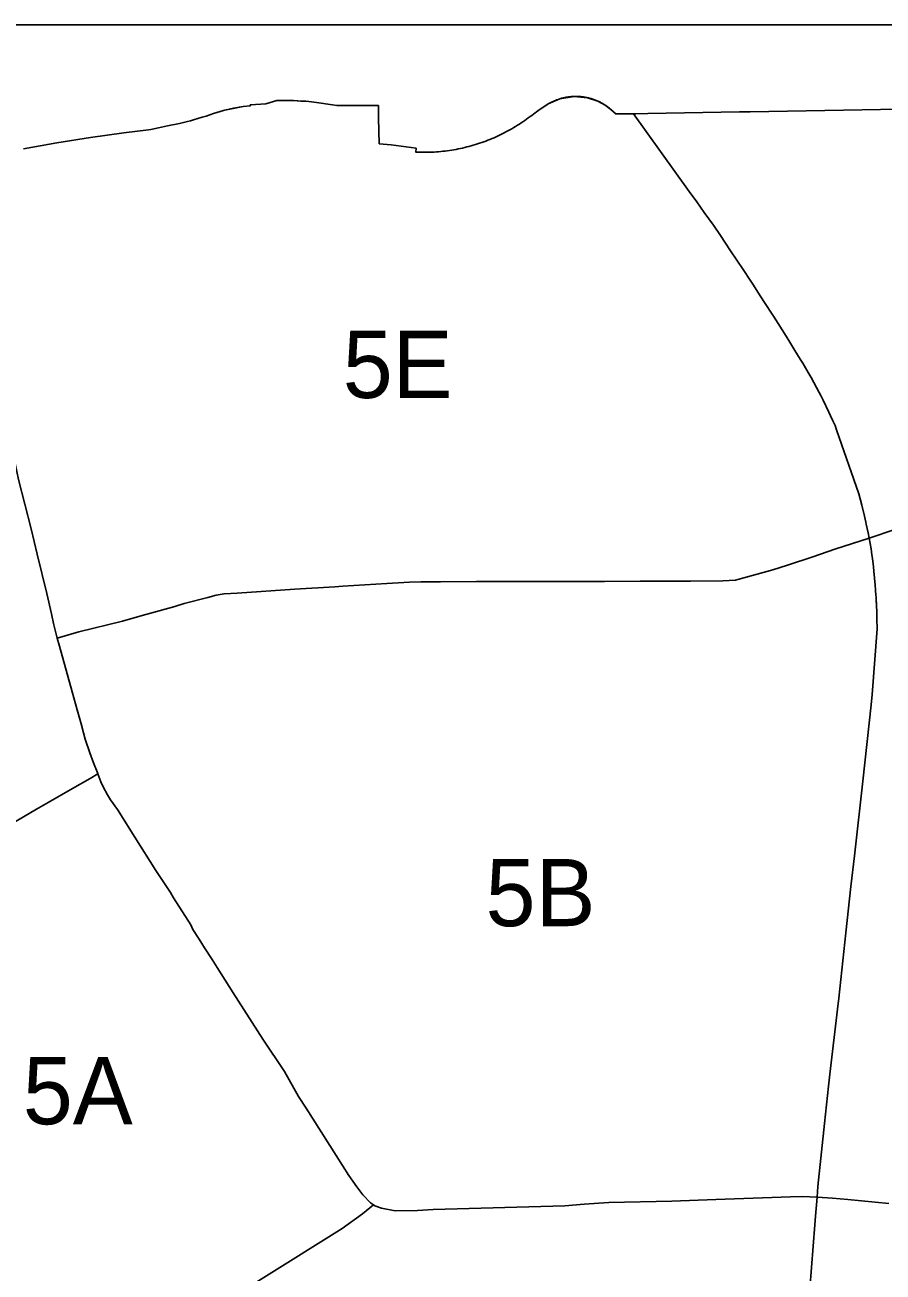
# Model space of a CAD drawing. Extents: x 152750 to 166250, y 378996 to 390000.
# Drawn here: x 159576 to 162130, y 386288 to 390000 of the extents above; entities that cross this region are included whole.
import ezdxf

# ---------------------------------------------------------------- set-up
doc = ezdxf.new("R2010")
doc.units = 0
doc.layers.add('BLT_Nummers', color=7, linetype='Continuous')
doc.layers.add('BLT_Shapes', color=7, linetype='Continuous')

msp = doc.modelspace()

# ---------------------------------------------------------------- linework, layer by layer
at = {"layer": 'BLT_Shapes'}
for p, q in [((163502.8, 390000), (157101, 390000)), ((160247.2, 389762.7), (160246.8, 389759.5)), ((160325.7, 389775.2), (160375.6, 389775.4)), ((160375.6, 389775.4), (160397.3, 389773.2)), ((160397.3, 389773.2), (160401, 389772.7)), ((160504.2, 389760.5), (160611.4, 389760.6)), ((160611.4, 389760.6), (160628.2, 389760.6)), ((161126.8, 389760.5), (161129.2, 389761.9)), ((161146, 389771.2), (161148.4, 389772.4)), ((161148.4, 389772.4), (161150.9, 389773.5)), ((161150.9, 389773.5), (161153.3, 389774.5)), ((161153.3, 389774.5), (161155.8, 389775.6)), ((161160.8, 389777.5), (161163.3, 389778.4)), ((161168.5, 389780.1), (161171, 389780.9)), ((161178.8, 389782.9), (161181.4, 389783.5)), ((161181.4, 389783.5), (161184.1, 389784.1)), ((161184.1, 389784.1), (161186.7, 389784.6)), ((161186.7, 389784.6), (161189.4, 389785.1)), ((161189.4, 389785.1), (161192, 389785.5)), ((161208.1, 389787.1), (161210.8, 389787.2)), ((161210.8, 389787.2), (161213.5, 389787.3)), ((161218.8, 389787.3), (161221.5, 389787.2)), ((161250.9, 389783.5), (161253.5, 389782.8)), ((161258.8, 389781.5), (161261.3, 389780.8)), ((161266.5, 389779.1), (161269, 389778.3)), ((161276.6, 389775.4), (161279.1, 389774.3)), ((161279.1, 389774.3), (161281.6, 389773.2)), ((161300.6, 389763), (161303.4, 389761.2)), ((161303.4, 389761.2), (161305.1, 389760.1)), ((160225.6, 389757.5), (160171.1, 389746.7)), ((160196.7, 389752.4), (160225.6, 389757.5)), ((160246.8, 389759.5), (160225.6, 389757.5)), ((161097.9, 389740.4), (161099.2, 389741.4)), ((161099.2, 389741.4), (161097.9, 389740.4)), ((161099.2, 389741.4), (161103.3, 389744.4)), ((161103.3, 389744.4), (161099.2, 389741.4)), ((161103.3, 389744.4), (161104.7, 389745.4)), ((161121.2, 389756.8), (161124.4, 389758.9)), ((161124.4, 389758.9), (161126.8, 389760.5)), ((161305.1, 389760.1), (161307.4, 389758.6)), ((161307.4, 389758.6), (161309.6, 389757)), ((161309.6, 389757), (161311.7, 389755.4)), ((161321.8, 389747.1), (161324.1, 389745.1)), ((161334.5, 389735), (161358.3, 389735.2)), ((161358.3, 389735.2), (161394, 389735.8)), ((161388, 389735.7), (161358.3, 389735.2)), ((161394, 389735.8), (161388, 389735.7)), ((161734.5, 389741.6), (161703, 389741.1)), ((159870.9, 389678.6), (159943.4, 389687.3)), ((159943.4, 389687.3), (159870.9, 389678.6)), ((159943.4, 389687.3), (159950.8, 389688.6)), ((159950.8, 389688.6), (159943.4, 389687.3)), ((159950.8, 389688.6), (159973.2, 389693.5)), ((159973.2, 389693.5), (159950.8, 389688.6)), ((159973.2, 389693.5), (160000, 389699.3)), ((160000, 389699.3), (159973.2, 389693.5)), ((160000, 389699.3), (160036.1, 389707.1)), ((160036.1, 389707.1), (160000, 389699.3)), ((160036.1, 389707.1), (160059.8, 389712.5)), ((160059.8, 389712.5), (160036.1, 389707.1)), ((161013.8, 389684.6), (161019.6, 389687.8)), ((161019.6, 389687.8), (161013.8, 389684.6)), ((160929.5, 389647.8), (160935.7, 389649.9)), ((160935.7, 389649.9), (160929.5, 389647.8)), ((160954.2, 389656.8), (160960.3, 389659.2)), ((160960.3, 389659.2), (160954.2, 389656.8)), ((160972.5, 389664.3), (160978.5, 389667)), ((160978.5, 389667), (160972.5, 389664.3)), ((160978.5, 389667), (160984.5, 389669.8)), ((160984.5, 389669.8), (160978.5, 389667)), ((159571.7, 389630.9), (159670.9, 389648.8)), ((159670.9, 389648.8), (159571.7, 389630.9)), ((160630.1, 389646.2), (160665.8, 389643.2)), ((160665.8, 389643.2), (160630.1, 389646.2)), ((160665.8, 389643.2), (160740.4, 389633.4)), ((160740.4, 389633.4), (160665.8, 389643.2)), ((160739.6, 389621.5), (160740.4, 389633.4)), ((160743.8, 389621.3), (160739.6, 389621.5)), ((160743.8, 389621.3), (160749.3, 389621.1)), ((160749.3, 389621.1), (160743.8, 389621.3)), ((160749.3, 389621.1), (160754.6, 389621)), ((160754.6, 389621), (160749.3, 389621.1)), ((160754.6, 389621), (160761.2, 389620.9)), ((160761.2, 389620.9), (160754.6, 389621)), ((160780.9, 389621.2), (160787.5, 389621.4)), ((160787.5, 389621.4), (160780.9, 389621.2)), ((160846.4, 389627.4), (160852.9, 389628.5)), ((160852.9, 389628.5), (160846.4, 389627.4)), ((161734.4, 389240.7), (161713.9, 389272.1)), ((161841.6, 389073.8), (161817.8, 389111.4)), ((161883.8, 389005.6), (161868.1, 389031)), ((161969.4, 388847.1), (161952.1, 388883)), ((161987.4, 388808.1), (161981, 388821.9)), ((161992.1, 388795.3), (161987.4, 388808.1)), ((162058.3, 388604.2), (161992.1, 388795.3)), ((162062.5, 388589.2), (162058.3, 388604.2)), ((162067.5, 388570.9), (162062.5, 388589.2)), ((162075.6, 388537.8), (162067.5, 388570.9)), ((162079.5, 388519.6), (162075.6, 388537.8)), ((162088.6, 388472.8), (162086, 388487.8)), ((162088.6, 388472.8), (162091.6, 388456.1)), ((161802.6, 388377.8), (161845.7, 388391.9)), ((161845.7, 388391.9), (161921.4, 388416.6)), ((162101.9, 388387.2), (162103.2, 388374.1)), ((160379.8, 388320.8), (160498.3, 388327.6)), ((160498.3, 388327.6), (160522.5, 388329.3)), ((161301.7, 388343.8), (161407.8, 388344.5)), ((161407.8, 388344.5), (161556.9, 388344.5)), ((161556.9, 388344.5), (161653.1, 388345.8)), ((161653.1, 388345.8), (161690.8, 388347.7)), ((162108.2, 388318), (162108.4, 388315.4)), ((162108.4, 388315.4), (162109.2, 388305.2)), ((159672.4, 388174.9), (159736.1, 388194.1)), ((159678.6, 388150.5), (159672.4, 388174.9)), ((159769.3, 387833.5), (159755.7, 387874.5)), ((159792.8, 387771.2), (159792.7, 387771.5)), ((159532.8, 387620.6), (159610.8, 387665.5)), ((160008.9, 387417.8), (160018.3, 387401.9)), ((160018.3, 387401.9), (160069.7, 387321.9)), ((160563.9, 386541.9), (160581.5, 386517.5)), ((161933.9, 386510.6), (161890.7, 386512.8)), ((161890.7, 386512.8), (161933.9, 386510.6)), ((162025.7, 386503.7), (162147.9, 386491.8))]:
    msp.add_line(p, q, dxfattribs=at)
for points in [[(160225.6, 389757.5), (160246.8, 389759.5), (160247.2, 389762.7), (160293.4, 389765.6), (160325.7, 389775.2)], [(160325.7, 389775.2), (160293.4, 389765.6), (160247.2, 389762.7)], [(160401, 389772.7), (160375.6, 389775.4), (160325.7, 389775.2)], [(160401, 389772.7), (160411.9, 389773.4), (160420.8, 389772.2)], [(160420.8, 389772.2), (160411.9, 389773.4), (160401, 389772.7)], [(160420.8, 389772.2), (160444.1, 389769.3), (160491.5, 389762.4), (160504.2, 389760.5)], [(160504.2, 389760.5), (160491.5, 389762.4), (160444.1, 389769.3), (160420.8, 389772.2)], [(160628.2, 389760.6), (160611.4, 389760.6), (160504.2, 389760.5)], [(160628.2, 389760.6), (160628.8, 389723.1), (160630.1, 389646.2)], [(160630.1, 389646.2), (160628.8, 389723.1), (160628.2, 389760.6)], [(161328.3, 389741.1), (161319.9, 389748.8), (161303.4, 389761.2), (161281.6, 389773.2), (161250.9, 389783.5), (161210.8, 389787.2), (161168.5, 389780.1), (161133.9, 389764.8), (161103.3, 389744.4)], [(161129.2, 389761.9), (161131.6, 389763.4), (161133.9, 389764.8), (161135.6, 389765.7), (161137.4, 389766.7), (161139.5, 389767.9), (161141.5, 389768.9), (161143.6, 389770), (161146, 389771.2)], [(161155.8, 389775.6), (161158.3, 389776.6), (161160.8, 389777.5)], [(161163.3, 389778.4), (161165.9, 389779.3), (161168.5, 389780.1)], [(161171, 389780.9), (161173.6, 389781.6), (161176.2, 389782.3), (161178.8, 389782.9)], [(161192, 389785.5), (161194.7, 389785.9), (161197.3, 389786.2), (161200, 389786.5), (161202.7, 389786.8)], [(161202.7, 389786.8), (161205.4, 389787), (161208.1, 389787.1)], [(161213.5, 389787.3), (161216.1, 389787.3), (161218.8, 389787.3)], [(161221.5, 389787.2), (161224.2, 389787.1), (161226.9, 389786.9), (161229.6, 389786.7), (161232.3, 389786.5), (161235, 389786.2)], [(161235, 389786.2), (161237.6, 389785.8), (161240.3, 389785.5)], [(161240.3, 389785.5), (161243, 389785), (161245.6, 389784.5), (161248.3, 389784), (161250.9, 389783.5)], [(161253.5, 389782.8), (161256.1, 389782.2), (161258.8, 389781.5)], [(161261.3, 389780.8), (161263.9, 389780), (161266.5, 389779.1)], [(161269, 389778.3), (161271.6, 389777.3), (161274.1, 389776.4), (161276.6, 389775.4)], [(161281.6, 389773.2), (161284, 389772.1), (161286.5, 389770.9), (161288.9, 389769.7), (161291.3, 389768.5), (161293.6, 389767.2), (161296, 389765.8)], [(161296, 389765.8), (161298.3, 389764.5), (161300.6, 389763)], [(161394, 389735.8), (161394.2, 389735.8), (161430.1, 389736.4), (161703, 389741.1), (161734.5, 389741.6), (162400.4, 389752.9), (162432.5, 389753.4), (162560.7, 389755.6), (162582.3, 389755.9), (162600.8, 389756.3), (162639.5, 389756.9), (163014.9, 389763.3), (163035.8, 389763.6), (163057.2, 389764), (163572.1, 389772.7), (163630.1, 389773.7)], [(160077.4, 389717.4), (160103.9, 389725.3), (160115.1, 389728.9)], [(160115.1, 389728.9), (160103.9, 389725.3), (160077.4, 389717.4)], [(160115.1, 389728.9), (160137.5, 389736), (160167.1, 389745.4), (160171.1, 389746.7), (160196.7, 389752.4)], [(160171.1, 389746.7), (160167.1, 389745.4), (160137.5, 389736), (160115.1, 389728.9)], [(161074.4, 389723.2), (161079.6, 389727), (161084.8, 389730.8), (161089.8, 389734.4)], [(161089.8, 389734.4), (161084.8, 389730.8), (161079.6, 389727), (161074.4, 389723.2)], [(161089.8, 389734.4), (161094.9, 389738.2), (161097.9, 389740.4)], [(161097.9, 389740.4), (161094.9, 389738.2), (161089.8, 389734.4)], [(161104.7, 389745.4), (161109.8, 389749), (161114.7, 389752.4), (161118, 389754.7), (161121.2, 389756.8)], [(161311.7, 389755.4), (161313.9, 389753.7), (161316, 389752.1), (161318, 389750.4), (161319.9, 389748.8), (161321.8, 389747.1)], [(161324.1, 389745.1), (161326.3, 389743), (161328.3, 389741.1)], [(161328.3, 389741.1), (161330.3, 389739.2), (161332.3, 389737.2), (161334.5, 389735)], [(161358.3, 389735.2), (161334.6, 389734.9), (161334.5, 389735), (161328.3, 389741.1)], [(161388, 389735.7), (161553.2, 389504.4), (161576.1, 389473), (161598.1, 389442.1), (161625.5, 389403.6), (161646.6, 389373.1), (161676.5, 389327.9), (161713.9, 389272.1), (161734.4, 389240.7), (161742.5, 389228.3), (161760.1, 389201.4), (161775.7, 389177.3), (161803.9, 389133.5), (161817.8, 389111.4), (161841.6, 389073.8), (161852.9, 389055.4), (161868.1, 389031), (161883.8, 389005.6), (161891.3, 388993.2), (161907.6, 388965.1), (161916.1, 388950.7), (161924.4, 388935.7), (161932.3, 388920.6), (161940.5, 388906), (161946.2, 388894.6), (161952.1, 388883), (161969.4, 388847.1), (161974.3, 388836.7), (161981, 388821.9), (161987.4, 388808.1), (161992.1, 388795.3), (162058.3, 388604.2), (162062.5, 388589.2), (162067.5, 388570.9), (162075.6, 388537.8), (162079.5, 388519.6), (162080.6, 388513.9), (162086, 388487.8), (162088.6, 388472.8)], [(161576.1, 389473), (161553.2, 389504.4), (161388, 389735.7)], [(161703, 389741.1), (161430.1, 389736.4), (161394.2, 389735.8), (161394, 389735.8)], [(162432.5, 389753.4), (162400.4, 389752.9), (161734.5, 389741.6)], [(160059.8, 389712.5), (160068.6, 389715), (160077.4, 389717.4)], [(160077.4, 389717.4), (160068.6, 389715), (160059.8, 389712.5)], [(161019.6, 389687.8), (161025.3, 389691.1), (161031, 389694.4), (161036.2, 389697.5), (161039.2, 389699.4)], [(161039.2, 389699.4), (161036.2, 389697.5), (161031, 389694.4), (161025.3, 389691.1), (161019.6, 389687.8)], [(161039.2, 389699.4), (161042.3, 389701.4), (161047.8, 389704.9)], [(161047.8, 389704.9), (161042.3, 389701.4), (161039.2, 389699.4)], [(161047.8, 389704.9), (161053.2, 389708.5), (161058.6, 389712.1), (161063.9, 389715.8), (161069.1, 389719.5), (161074.4, 389723.2)], [(161074.4, 389723.2), (161069.1, 389719.5), (161063.9, 389715.8), (161058.6, 389712.1), (161053.2, 389708.5), (161047.8, 389704.9)], [(159670.9, 389648.8), (159770.8, 389664.8), (159870.9, 389678.6)], [(159870.9, 389678.6), (159770.8, 389664.8), (159670.9, 389648.8)], [(160935.7, 389649.9), (160941.9, 389652.2), (160948.1, 389654.4), (160954.2, 389656.8)], [(160954.2, 389656.8), (160948.1, 389654.4), (160941.9, 389652.2), (160935.7, 389649.9)], [(160960.3, 389659.2), (160966.4, 389661.8), (160972.5, 389664.3)], [(160972.5, 389664.3), (160966.4, 389661.8), (160960.3, 389659.2)], [(160984.5, 389669.8), (160990.4, 389672.6), (160996.3, 389675.5)], [(160996.3, 389675.5), (160990.4, 389672.6), (160984.5, 389669.8)], [(160996.3, 389675.5), (161002.2, 389678.4), (161008, 389681.5), (161013.8, 389684.6)], [(161013.8, 389684.6), (161008, 389681.5), (161002.2, 389678.4), (160996.3, 389675.5)], [(160740.4, 389633.4), (160739.6, 389621.5), (160743.8, 389621.3)], [(160761.2, 389620.9), (160767.8, 389620.9), (160774.4, 389621), (160780.9, 389621.2)], [(160780.9, 389621.2), (160774.4, 389621), (160767.8, 389620.9), (160761.2, 389620.9)], [(160787.5, 389621.4), (160794.1, 389621.8), (160800.7, 389622.2), (160807.2, 389622.7)], [(160807.2, 389622.7), (160800.7, 389622.2), (160794.1, 389621.8), (160787.5, 389621.4)], [(160807.2, 389622.7), (160813.8, 389623.3), (160820.3, 389623.9), (160826.9, 389624.7)], [(160826.9, 389624.7), (160820.3, 389623.9), (160813.8, 389623.3), (160807.2, 389622.7)], [(160826.9, 389624.7), (160833.4, 389625.5), (160839.9, 389626.4), (160846.4, 389627.4)], [(160846.4, 389627.4), (160839.9, 389626.4), (160833.4, 389625.5), (160826.9, 389624.7)], [(160852.9, 389628.5), (160859.4, 389629.7), (160865.9, 389630.9)], [(160865.9, 389630.9), (160859.4, 389629.7), (160852.9, 389628.5)], [(160865.9, 389630.9), (160872.3, 389632.3), (160878.7, 389633.7), (160885.2, 389635.2)], [(160885.2, 389635.2), (160878.7, 389633.7), (160872.3, 389632.3), (160865.9, 389630.9)], [(160885.2, 389635.2), (160891.5, 389636.7), (160897.9, 389638.4), (160904.3, 389640.1)], [(160904.3, 389640.1), (160897.9, 389638.4), (160891.5, 389636.7), (160885.2, 389635.2)], [(160904.3, 389640.1), (160910.6, 389641.9), (160916.9, 389643.8)], [(160916.9, 389643.8), (160910.6, 389641.9), (160904.3, 389640.1)], [(160916.9, 389643.8), (160923.2, 389645.8), (160929.5, 389647.8)], [(160929.5, 389647.8), (160923.2, 389645.8), (160916.9, 389643.8)], [(159435.7, 389602.7), (159445.7, 389422.8), (159454.2, 389281.4), (159455, 389268.9), (159465.3, 389176.8), (159473.4, 389120), (159473.9, 389088.3), (159489.7, 388991.7), (159522.2, 388814.1), (159556.9, 388647.5), (159594.9, 388500.2), (159612.6, 388424.8), (159641, 388307.4), (159654.7, 388247.3), (159661.5, 388218), (159672.4, 388174.9)], [(161625.5, 389403.6), (161598.1, 389442.1), (161576.1, 389473)], [(161713.9, 389272.1), (161676.5, 389327.9), (161646.6, 389373.1), (161625.5, 389403.6)], [(161775.7, 389177.3), (161760.1, 389201.4), (161742.5, 389228.3), (161734.4, 389240.7)], [(161817.8, 389111.4), (161803.9, 389133.5), (161775.7, 389177.3)], [(161868.1, 389031), (161852.9, 389055.4), (161841.6, 389073.8)], [(159594.9, 388500.2), (159556.9, 388647.5), (159522.2, 388814.1), (159489.7, 388991.7)], [(161916.1, 388950.7), (161907.6, 388965.1), (161891.3, 388993.2), (161883.8, 389005.6)], [(161932.3, 388920.6), (161924.4, 388935.7), (161916.1, 388950.7)], [(161952.1, 388883), (161946.2, 388894.6), (161940.5, 388906), (161932.3, 388920.6)], [(161981, 388821.9), (161974.3, 388836.7), (161969.4, 388847.1)], [(163402.6, 388500), (163158.8, 388525.2), (163068.9, 388535.3), (162959.7, 388547.7), (162952.6, 388548.5), (162751.9, 388570.9), (162693.6, 388577.4), (162586.8, 388594.8), (162559.9, 388608.6), (162508.9, 388645.2), (162498.3, 388632.5), (162485.7, 388620.4), (162466.4, 388605.7), (162458.1, 388601.4), (162310.5, 388546), (162233.8, 388520.7), (162180.4, 388502.8), (162165.8, 388498), (162088.6, 388472.8)], [(159672.4, 388174.9), (159661.5, 388218), (159654.7, 388247.3), (159641, 388307.4), (159612.6, 388424.8), (159594.9, 388500.2)], [(162086, 388487.8), (162080.6, 388513.9), (162079.5, 388519.6)], [(162088.6, 388472.8), (162165.8, 388498), (162180.4, 388502.8)], [(162088.6, 388472.8), (161987.3, 388439.6), (161921.4, 388416.6), (161845.7, 388391.9), (161802.6, 388377.8), (161698.6, 388349), (161690.8, 388347.7), (161653.1, 388345.8), (161556.9, 388344.5), (161407.8, 388344.5), (161301.7, 388343.8), (161225.4, 388343.5), (161013.3, 388343.2), (160920.7, 388343.2), (160812.8, 388342.8), (160755, 388342.5), (160720.9, 388341.2), (160653.8, 388337.6), (160522.5, 388329.3), (160498.3, 388327.6), (160379.8, 388320.8), (160207.6, 388309.1), (160168.9, 388307.1), (160145.5, 388302.5), (160120.5, 388296), (160049.7, 388277.5), (160022.4, 388269.1), (159918.1, 388239.8), (159866.5, 388225.8), (159736.1, 388194.1), (159672.4, 388174.9)], [(161921.4, 388416.6), (161987.3, 388439.6), (162088.6, 388472.8)], [(161933.9, 386510.6), (161936.4, 386542.6), (161956.3, 386730.3), (161968.5, 386841), (161972.3, 386877.2), (161994.8, 387070.3), (161998.4, 387103.2), (162019.5, 387297.7), (162034.8, 387435.9), (162045.1, 387527.1), (162070.3, 387748.8), (162095.1, 387976.2), (162098.3, 388007.3), (162113, 388202.9), (162112.3, 388231.9), (162111.6, 388256), (162111.3, 388268.6), (162110.6, 388280.1), (162110.4, 388283.1), (162109.7, 388294.8), (162109.2, 388305.2), (162108.4, 388315.4), (162108.2, 388318), (162107, 388333.9), (162106.3, 388342), (162105.4, 388353), (162103.2, 388374.1), (162101.9, 388387.2), (162098.7, 388412.3), (162097.3, 388422.4), (162094.9, 388440.7), (162091.6, 388456.1), (162088.6, 388472.8)], [(162091.6, 388456.1), (162094.9, 388440.7), (162097.3, 388422.4)], [(162097.3, 388422.4), (162098.7, 388412.3), (162101.9, 388387.2)], [(161690.8, 388347.7), (161698.6, 388349), (161802.6, 388377.8)], [(162103.2, 388374.1), (162105.4, 388353), (162106.3, 388342)], [(160120.5, 388296), (160145.5, 388302.5), (160168.9, 388307.1), (160207.6, 388309.1), (160379.8, 388320.8)], [(160522.5, 388329.3), (160653.8, 388337.6), (160720.9, 388341.2), (160755, 388342.5)], [(160755, 388342.5), (160812.8, 388342.8), (160920.7, 388343.2), (161013.3, 388343.2)], [(161013.3, 388343.2), (161225.4, 388343.5), (161301.7, 388343.8)], [(162106.3, 388342), (162107, 388333.9), (162108.2, 388318)], [(159736.1, 388194.1), (159866.5, 388225.8), (159918.1, 388239.8), (160022.4, 388269.1), (160049.7, 388277.5), (160120.5, 388296)], [(162109.2, 388305.2), (162109.7, 388294.8), (162110.4, 388283.1)], [(162110.4, 388283.1), (162110.6, 388280.1), (162111.3, 388268.6)], [(162111.3, 388268.6), (162111.6, 388256), (162112.3, 388231.9)], [(162112.3, 388231.9), (162113, 388202.9), (162098.3, 388007.3), (162095.1, 387976.2), (162070.3, 387748.8), (162045.1, 387527.1), (162034.8, 387435.9)], [(159672.4, 388174.9), (159678.6, 388150.5), (159716.7, 388014.6), (159731.7, 387961.3), (159743.4, 387919.3), (159750.2, 387893.3), (159755.7, 387874.5), (159769.3, 387833.5), (159780.1, 387803.3), (159792.7, 387771.5), (159792.8, 387771.2)], [(159743.4, 387919.3), (159731.7, 387961.3), (159716.7, 388014.6), (159678.6, 388150.5)], [(159755.7, 387874.5), (159750.2, 387893.3), (159743.4, 387919.3)], [(159792.7, 387771.5), (159780.1, 387803.3), (159769.3, 387833.5)], [(159792.8, 387771.2), (159770, 387757.1), (159717.4, 387727.2), (159645.6, 387685.3), (159610.8, 387665.5), (159532.8, 387620.6), (159489.9, 387595.9), (159445.1, 387570.3), (159389.6, 387538.7), (159297, 387485.8), (159274.2, 387473.7), (159250.2, 387460.1), (159219, 387441.9), (159089.4, 387364.2), (159062, 387347.3), (158982.2, 387298), (158946.8, 387276.1), (158916.2, 387258.2), (158893.9, 387244.6), (158832.4, 387209.5)], [(159717.4, 387727.2), (159770, 387757.1), (159792.8, 387771.2)], [(160613.2, 386488.3), (160604.9, 386494.4), (160581.5, 386517.5), (160563.9, 386541.9), (160540.4, 386575), (160502.1, 386635.1), (160413.4, 386775.9), (160390.6, 386811), (160348.4, 386885.4), (160284.7, 386980.7), (160195.7, 387119.4), (160148.6, 387194.2), (160133.7, 387218.6), (160110.6, 387252.7), (160094.4, 387278.7), (160075.5, 387308), (160069.7, 387321.9), (160018.3, 387401.9), (160008.9, 387417.8), (159965.7, 387483.5), (159902.9, 387582.6), (159851.9, 387664.5), (159831.1, 387693.1), (159821.6, 387708.7), (159808.7, 387731.8), (159801.8, 387747.4), (159792.8, 387771.2)], [(159792.8, 387771.2), (159801.8, 387747.4), (159808.7, 387731.8)], [(159610.8, 387665.5), (159645.6, 387685.3), (159717.4, 387727.2)], [(159808.7, 387731.8), (159821.6, 387708.7), (159831.1, 387693.1), (159851.9, 387664.5), (159902.9, 387582.6)], [(159902.9, 387582.6), (159965.7, 387483.5), (160008.9, 387417.8)], [(162034.8, 387435.9), (162019.5, 387297.7), (161998.4, 387103.2), (161994.8, 387070.3), (161972.3, 386877.2)], [(160069.7, 387321.9), (160075.5, 387308), (160094.4, 387278.7), (160110.6, 387252.7), (160133.7, 387218.6), (160148.6, 387194.2), (160195.7, 387119.4)], [(160195.7, 387119.4), (160284.7, 386980.7), (160348.4, 386885.4), (160390.6, 386811)], [(161972.3, 386877.2), (161968.5, 386841), (161956.3, 386730.3), (161936.4, 386542.6), (161933.9, 386510.6)], [(160390.6, 386811), (160413.4, 386775.9), (160502.1, 386635.1)], [(160502.1, 386635.1), (160540.4, 386575), (160563.9, 386541.9)], [(160581.5, 386517.5), (160604.9, 386494.4), (160613.2, 386488.3)], [(161890.7, 386512.8), (161855.4, 386512.2), (161632.5, 386504), (161501.2, 386499.1), (161313.8, 386494.9), (161240.8, 386490.3), (161183, 386485.3), (160791.2, 386474.3), (160744.4, 386471.7), (160678.5, 386470.4), (160637.7, 386478.5), (160617.2, 386485.3), (160613.2, 386488.3)], [(160791.2, 386474.3), (161183, 386485.3), (161240.8, 386490.3), (161313.8, 386494.9), (161501.2, 386499.1), (161632.5, 386504)], [(161632.5, 386504), (161855.4, 386512.2), (161890.7, 386512.8)], [(161773.9, 384860.2), (161794.2, 384939.2), (161831.9, 385125.3), (161835, 385142.9), (161843.4, 385219.2), (161851.8, 385318.4), (161859.1, 385428.7), (161872.2, 385624.7), (161875.4, 385672.6), (161893.7, 385933.6), (161902.1, 386079.3), (161912.3, 386237.6), (161927.2, 386428.6), (161929.6, 386454.8), (161933.9, 386510.6)], [(161933.9, 386510.6), (161929.6, 386454.8), (161927.2, 386428.6), (161912.3, 386237.6)], [(162147.9, 386491.8), (162025.7, 386503.7), (161979.9, 386508.2), (161933.9, 386510.6)], [(161933.9, 386510.6), (161979.9, 386508.2), (162025.7, 386503.7)], [(160613.2, 386488.3), (160580.8, 386461.3), (160520.7, 386417.7), (160286.8, 386271.8), (160108.2, 386160.3), (160026.6, 386109.9), (159998.4, 386092.3), (159847.6, 385998.4), (159699.8, 385906.1), (159663.3, 385882.1), (159662.6, 385881.4)], [(160286.8, 386271.8), (160520.7, 386417.7), (160580.8, 386461.3), (160613.2, 386488.3)], [(160613.2, 386488.3), (160617.2, 386485.3), (160637.7, 386478.5), (160678.5, 386470.4)], [(160678.5, 386470.4), (160744.4, 386471.7), (160791.2, 386474.3)]]:
    msp.add_lwpolyline(points, dxfattribs=at)

# ---------------------------------------------------------------- texts
at = {"layer": 'BLT_Nummers'}
for s, p in [('5E', (160522.2, 388889.7)), ('5B', (160947.3, 387317.5)), ('5A', (159569.8, 386727.9))]:
    msp.add_text(s, height=200, dxfattribs=at).set_placement(p)

doc.saveas('drawing.dxf')
